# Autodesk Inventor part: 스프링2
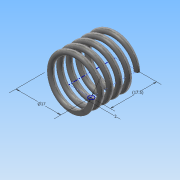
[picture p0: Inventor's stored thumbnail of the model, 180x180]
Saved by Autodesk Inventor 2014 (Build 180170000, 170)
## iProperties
Created: 2016-01
Part Number: 스프링2
Material: 강철, 탄소
Document SubType Name: Modeling
Designer: Administrator
Density: 7.87 g/cm^3
Appearance: 반연마
Mass: 6.45107 g
Surface Area: 16.7052 cm^2
Volume: 0.819704 cm^3
Author: Administrator
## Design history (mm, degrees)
sketch "스케치1"
  geometry: L1 (0, 0)-(8.5, 0); L2 (8.5, 0)-(8.5, 17.5); L3 (8.5, 17.5)-(0, 17.5); L4 (0, 17.5)-(0, 0); C1 r 1 at (8.5, 0)
  constraints: 8 end point, 2 parallel, 1 centre point, 1 coincident, 1 horizontal, 1 perpendicular
  dimensions: "d0" = 17.5 distance of L1.end L2.end (derived); "d1" = 2 diameter of C1; "d2" = 17 diameter of L2 L4
feature "코일1" sketch "스케치1" pitch "d3" = 10; turns "d5" = 5; dims "d4" = 17.5 (= d0), "d6" = 0, angle "d7" = 90 deg, angle "d8" = 90 deg, "d9" = 0, "d10" = 0
node "작업 평면1"
sketch "스케치2"
  geometry: L1 (7.5, 0)-(9.5, 0) reference; 1 further point
  constraints: 1 horizontal alignment
extrude "돌출1" cut sketch "스케치2" distance "d12" = 10; taper "d13" = 0 deg
node "작업 평면2"
sketch "스케치3"
  geometry: L1 (-7.5, 0)-(-9.5, 0) reference; 1 further point
  constraints: 1 horizontal alignment
extrude "돌출2" cut sketch "스케치3" distance "d15" = 10; taper "d16" = 0 deg
node "솔리드1"
node "절단 모서리 투영1"
node "절단 모서리 투영2"
other parameters: "d11" = 0, "d14" = -17.5 (= -d0)
